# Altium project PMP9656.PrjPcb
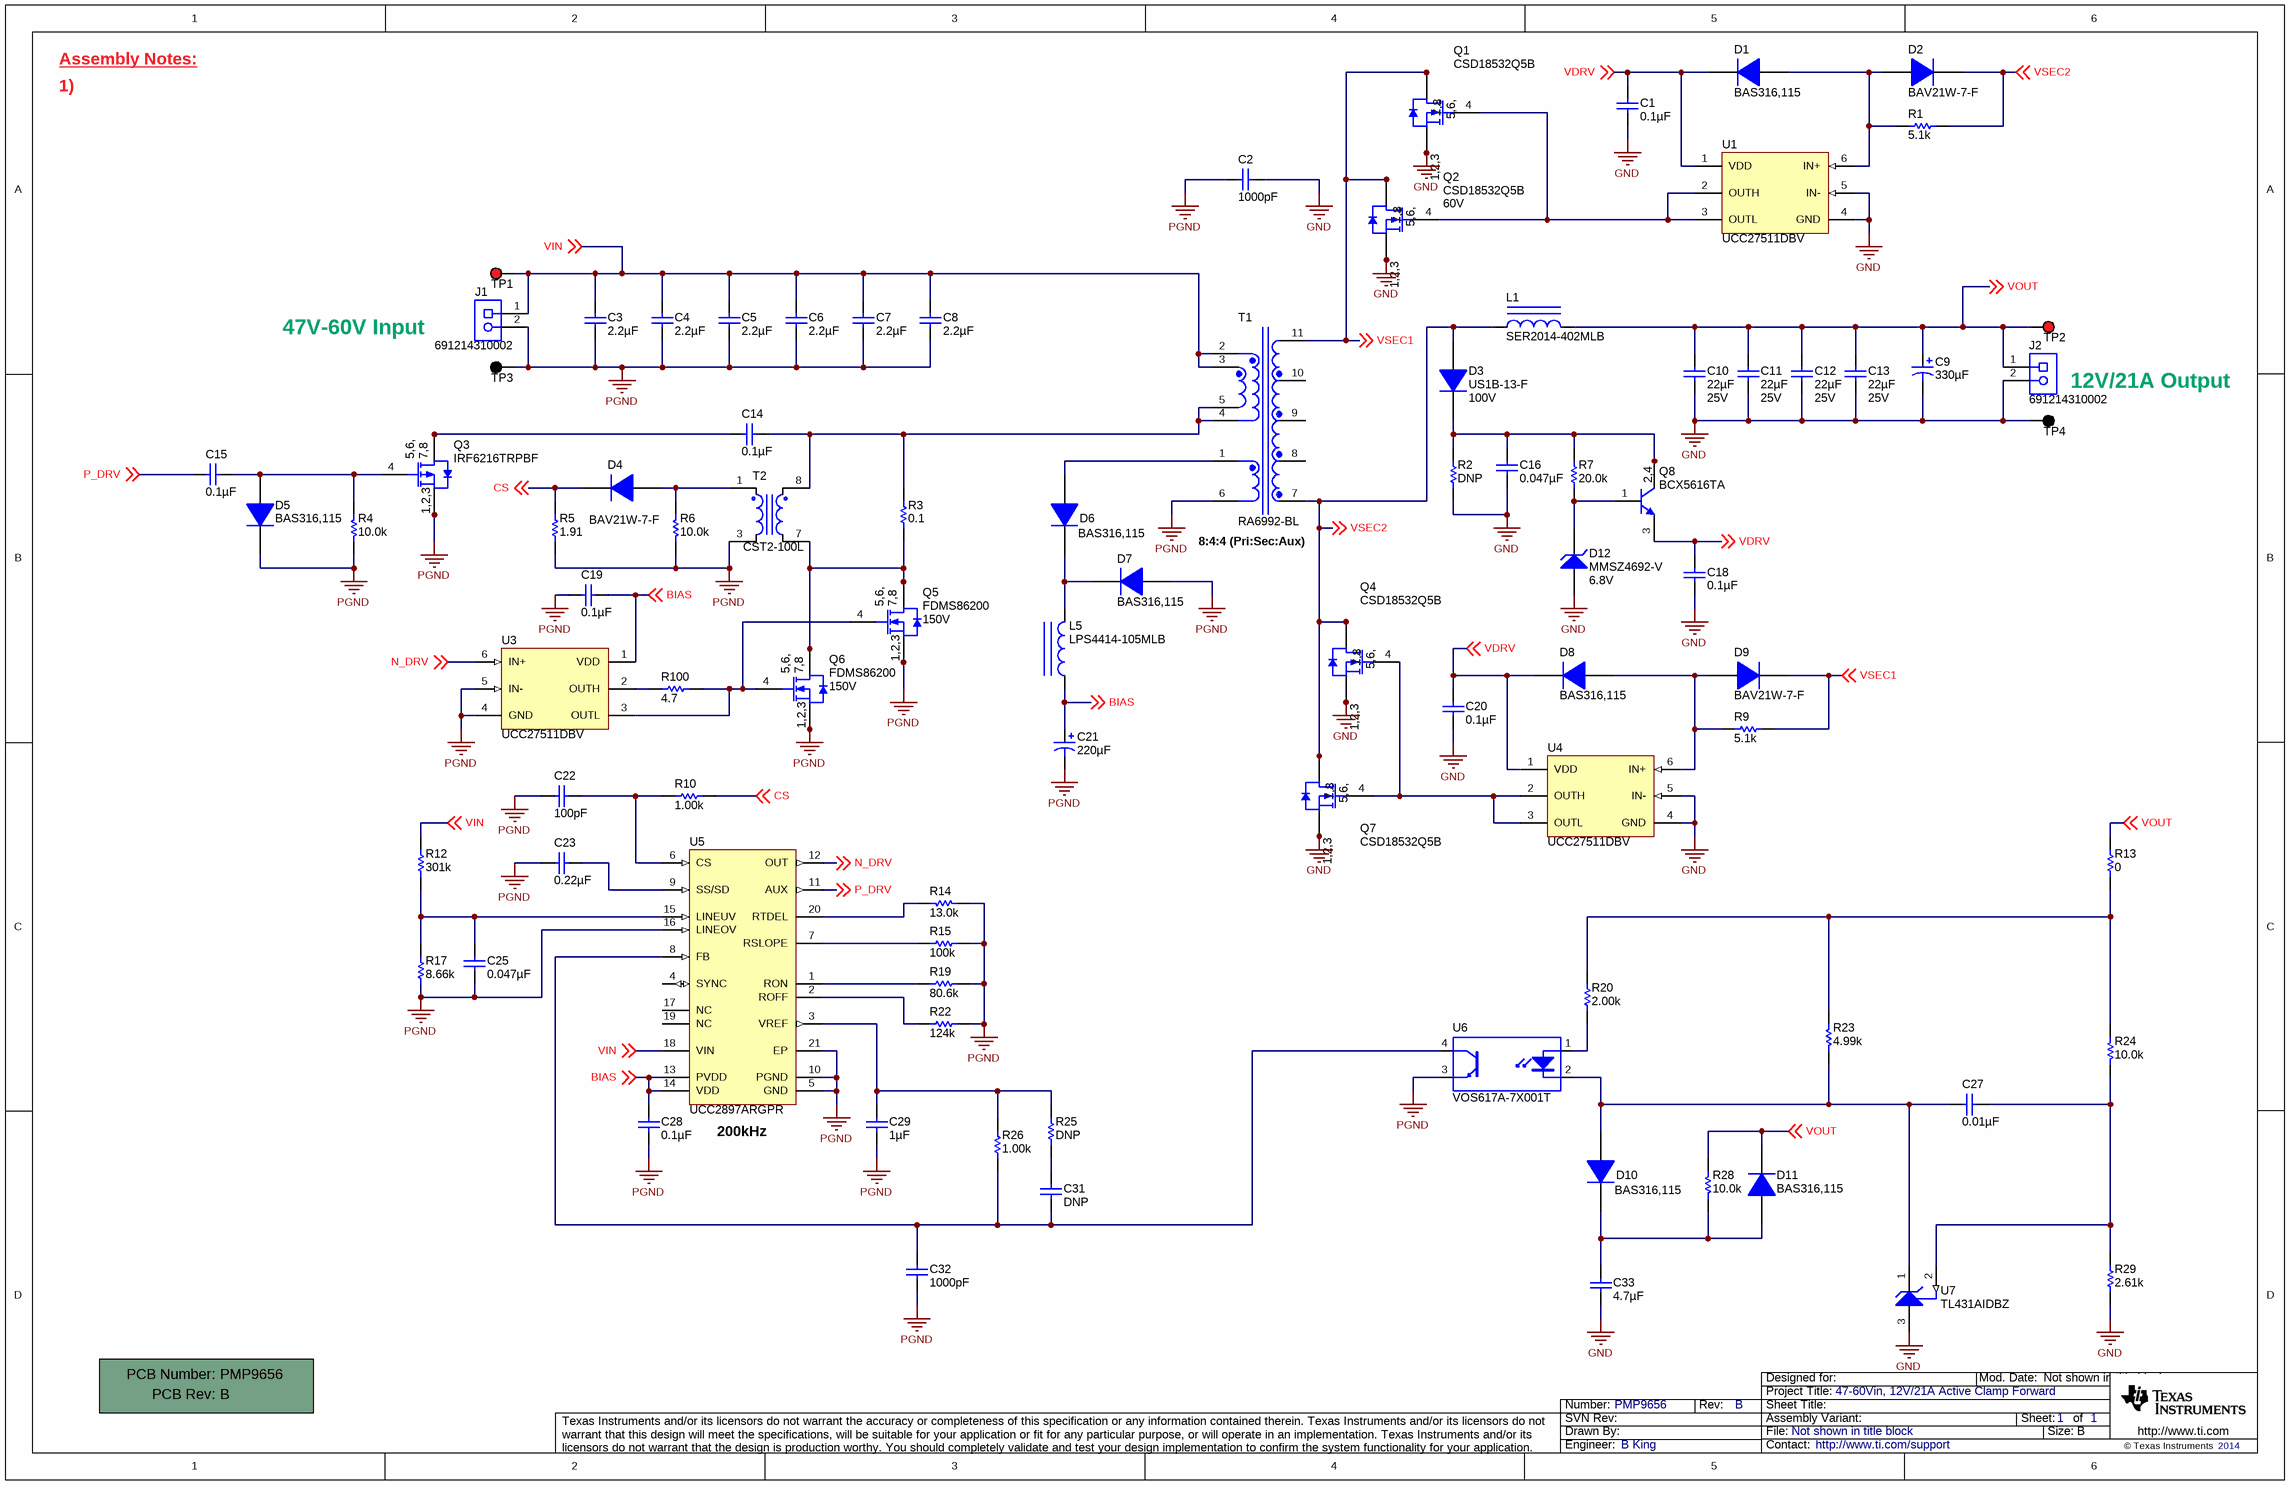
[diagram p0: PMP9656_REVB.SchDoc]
TechSupport: http://www.ti.com/support; SCH_Rev: B; PRJ_Title: 47-60Vin, 12V/21A Active Clamp Forward; PRJ_Number: PMP9656; PRJ_Engineer: B King; PCB_Rev: B; PCB_Layout: B King; CopyrightYear: 2014
1 sheet, 90 parts. Net scope: global (net labels, ports and power ports of the same name join across sheets).
Board file: PMP9656_REVB.PcbDoc

## Sheet PMP9656_REVB.SchDoc
size 431 x 279 mm; Date: Not shown in title block; ApprovedBy: Not shown in title block; CheckedBy: Not shown in title block; Author: Not shown in title block; CompanyName: Not shown in title block; Engineer: Not shown in title block; Organization: Not shown in title block; Address1: Not shown in title block; Address2: Not shown in title block; Address3: Not shown in title block; Address4: Not shown in title block; DocumentNumber: 1; Revision: Use project parameter SCH_Rev; SheetNumber: 1; SheetTotal: 1; PageSetup: Record=PageOptions¦CenterHorizontal=True¦CenterVertical=True¦PrintScale=1.00¦XCorrection=1.00¦YCorrection=1.00¦PrintKind=0¦BorderSize=5000000¦LeftOffset=0¦BottomOffset=0¦Orientation=2¦PaperLength=1000¦PaperWidth=1000¦Scale=100¦PaperSource=15¦PrintQuality=600¦MediaType=1¦DitherType=10¦PaperKind=Letter¦PrintScaleMode=1

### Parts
!PCB1  Printed Circuit Board  (value not drawn)  (mechanical)
C1  ValueDisplayed: 0.1µF  [0402L]  (hidden comment: C1005X7R1H104M)
C2  ValueDisplayed: 1000pF  [1808_L]  (hidden comment: STD)
C3  ValueDisplayed: 2.2µF  [1210L]  (hidden comment: GRM32ER72A225KA35L)
C4  ValueDisplayed: 2.2µF  [1210L]  (hidden comment: GRM32ER72A225KA35L)
C5  ValueDisplayed: 2.2µF  [1210L]  (hidden comment: GRM32ER72A225KA35L)
C6  ValueDisplayed: 2.2µF  [1210L]  (hidden comment: GRM32ER72A225KA35L)
C7  ValueDisplayed: 2.2µF  [1210L]  (hidden comment: GRM32ER72A225KA35L)
C8  ValueDisplayed: 2.2µF  [1210L]  (hidden comment: GRM32ER72A225KA35L)
C9  ValueDisplayed: 330µF  [SM_RADIAL_10AMM]  (hidden comment: 16SVP330M)
C10  ValueDisplayed: 22µF  Value2: 25V  [1210L]  (hidden comment: GRM32ER61E226KE15L)
C11  ValueDisplayed: 22µF  Value2: 25V  [1210L]  (hidden comment: GRM32ER61E226KE15L)
C12  ValueDisplayed: 22µF  Value2: 25V  [1210L]  (hidden comment: GRM32ER61E226KE15L)
C13  ValueDisplayed: 22µF  Value2: 25V  [1210L]  (hidden comment: GRM32ER61E226KE15L)
C14  ValueDisplayed: 0.1µF  [1206L]  (hidden comment: C3216X7R2E104K)
C15  ValueDisplayed: 0.1µF  [0402L]  (hidden comment: C1005X7R1H104M)
C16  ValueDisplayed: 0.047µF  [0805L]  (hidden comment: C2012X7R2A473K)
C18  ValueDisplayed: 0.1µF  [0402L]  (hidden comment: GRM155R61H104ME14D)
C19  ValueDisplayed: 0.1µF  [0402L]  (hidden comment: C1005X7R1H104M)
C20  ValueDisplayed: 0.1µF  [0402L]  (hidden comment: C1005X7R1H104M)
C21  ValueDisplayed: 220µF  [SM_RADIAL_D8]  (hidden comment: EEE-FK1C221XP)
C22  ValueDisplayed: 100pF  [0402L]  (hidden comment: CC0402KRX7R9BB101)
C23  ValueDisplayed: 0.22µF  [0402L]  (hidden comment: GRM155R61A224KE19D)
C25  ValueDisplayed: 0.047µF  [0402L]  (hidden comment: GRM155R71E473KA88D)
C27  ValueDisplayed: 0.01µF  [0402L]  (hidden comment: C1005X7R1E103K)
C28  ValueDisplayed: 0.1µF  [0402L]  (hidden comment: C1005X7R1H104M)
C29  ValueDisplayed: 1µF  [0402L]  (hidden comment: GRM155R61A105KE15D)
C31  value DNP  [0402L]  (hidden comment: N/A)
C32  ValueDisplayed: 1000pF  [0402L]  (hidden comment: C1005X7R1H102K)
C33  ValueDisplayed: 4.7µF  [1206L]  (hidden comment: C3216X7R1E475K)
D1  BAS316,115  [sod-323]
D2  BAV21W-7-F  [SOD-123]
D3  US1B-13-F  value 100V  [SMA]
D4  BAV21W-7-F  [SOD-123]
D5  BAS316,115  [sod-323]
D6  BAS316,115  [sod-323]
D7  BAS316,115  [sod-323]
D8  BAS316,115  [sod-323]
D9  BAV21W-7-F  [SOD-123]
D10  BAS316,115  [sod-323]
D11  BAS316,115  [sod-323]
D12  MMSZ4692-V  value 6.8V  [SOD-123]
J1  691214310002  [Wurth_691214310002]
J2  691214310002  [Wurth_691214310002]
L1  SER2014-402MLB  [SER2014]
L5  LPS4414-105MLB  [LPS4414]
Q1  CSD18532Q5B  [TRANS_NexFET_Q5B]
Q2  CSD18532Q5B  value 60V  [TRANS_NexFET_Q5B]
Q3  IRF6216TRPBF  [SO-8L]
Q4  CSD18532Q5B  [TRANS_NexFET_Q5B]
Q5  FDMS86200  value 150V  [TRANS_Fairchild_PQFN08A]
Q6  FDMS86200  value 150V  [TRANS_Fairchild_PQFN08A]
Q7  CSD18532Q5B  [TRANS_NexFET_Q5B]
Q8  BCX5616TA  [SOT-89-3]
R1  value 5.1k  [0805L]  (hidden comment: CRCW08055K10JNEA)
R2  value DNP  [1210L]  (hidden comment: N/A)
R3  value 0.1  [0805L]  (hidden comment: ERJ-6RSJR10V)
R4  value 10.0k  [0402L]  (hidden comment: CRCW040210K0FKED)
R5  value 1.91  [0805L]  (hidden comment: RC0805FR-071R91L)
R6  value 10.0k  [0402L]  (hidden comment: CRCW040210K0FKED)
R7  value 20.0k  [0805L]  (hidden comment: CRCW080520K0FKEA)
R9  value 5.1k  [0805L]  (hidden comment: CRCW08055K10JNEA)
R10  value 1.00k  [0402L]  (hidden comment: CRCW04021K00FKED)
R12  value 301k  [0402L]  (hidden comment: CRCW0402301KFKED)
R13  value 0  [0402L]  (hidden comment: CRCW04020000Z0ED)
R14  value 13.0k  [0402L]  (hidden comment: CRCW040213K0FKED)
R15  value 100k  [0402L]  (hidden comment: CRCW0402100KFKED)
R17  value 8.66k  [0402L]  (hidden comment: CRCW04028K66FKED)
R19  value 80.6k  [0402L]  (hidden comment: CRCW040280K6FKED)
R20  value 2.00k  [0402L]  (hidden comment: CRCW04022K00FKED)
R22  value 124k  [0402L]  (hidden comment: CRCW0402124KFKED)
R23  value 4.99k  [0402L]  (hidden comment: CRCW04024K99FKED)
R24  value 10.0k  [0402L]  (hidden comment: CRCW040210K0FKED)
R25  value DNP  [0402L]  (hidden comment: N/A)
R26  value 1.00k  [0402L]  (hidden comment: CRCW04021K00FKED)
R28  value 10.0k  [0402L]  (hidden comment: CRCW040210K0FKED)
R29  value 2.61k  [0402L]  (hidden comment: CRCW04022K61FKED)
R100  value 4.7  [0402L]  (hidden comment: CRCW04024R70JNED)
T1  RA6992-BL  [Coilcraft_RA6992-BL]
T2  CST2-100L  [XFMR_COILCRAFT_8X8p13MM6P]
TP1  5000  [Keystone5000]  (value not drawn)
TP2  5000  [Keystone5000]  (value not drawn)
TP3  5011  [Keystone5011]  (value not drawn)
TP4  5011  [Keystone5011]  (value not drawn)
U1  UCC27511DBV  [DBV0006A_M]
U3  UCC27511DBV  [DBV0006A_M]
U4  UCC27511DBV  [DBV0006A_M]
U5  UCC2897ARGPR  [RGP0020D]
U6  VOS617A-7X001T  [SSOP-4_VISHAY]
U7  TL431AIDBZ  [DBZ0003A_N]

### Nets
GND: C1.2 C2.1 C9.2(-) C10.2 C11.2 C12.2 C13.2 C16.2 C18.2 C20.2 C33.2 D12.2(A) J2.2 Q1.1(S) Q1.2(S) Q1.3(S) Q2.1(S) Q2.2(S) Q2.3(S) Q4.1(S) Q4.2(S) Q4.3(S) Q7.1(S) Q7.2(S) Q7.3(S) R2.1 R29.1 TP4.1 U1.4(GND) U1.5(IN-) U4.4(GND) U4.5(IN-) U7.3(ANODE)
PGND: C2.2 C3.2 C4.2 C5.2 C6.2 C7.2 C8.2 C19.1 C21.2(-) C22.1 C23.1 C25.1 C28.2 C29.2 C32.2 D5.1(K) D7.2(A) J1.2 Q3.1(S) Q3.2(S) Q3.3(S) Q5.1(S) Q5.2(S) Q5.3(S) Q6.1(S) Q6.2(S) Q6.3(S) R4.1 R5.1 R6.1 R14.1 R15.1 R17.1 R19.1 R22.1 T1.6 T2.3 TP3.1 U3.4(GND) U3.5(IN-) U5.5(GND) U5.10(PGND) U5.16(LINEOV) U5.21(EP) U6.3(E)
BIAS: C19.2 C21.1(+) C28.1 L5.1 U3.1(VDD) U5.13(PVDD) U5.14(VDD) ; off-sheet BIAS
CS: D4.1(K) R5.2 R10.1 ; off-sheet CS
N_DRV: U3.6(IN+) U5.12(OUT) ; off-sheet N_DRV
P_DRV: C15.1 U5.11(AUX) ; off-sheet P_DRV
VDRV: C1.1 C18.1 C20.1 D1.1(K) D8.1(K) Q8.3(E) U1.1(VDD) U4.1(VDD) ; off-sheet VDRV
VIN: C3.1 C4.1 C5.1 C6.1 C7.1 C8.1 J1.1 R12.2 T1.2 T1.3 TP1.1 U5.18(VIN) ; off-sheet VIN
VOUT: C9.1(+) C10.1 C11.1 C12.1 C13.1 D11.1(K) J2.1 L1.2 R13.1 R28.2 TP2.1 ; off-sheet VOUT
VSEC1: D9.1(K) Q1.5(D) Q1.6(D) Q1.7(D) Q1.8(D) Q2.5(D) Q2.6(D) Q2.7(D) Q2.8(D) R9.1 T1.11 ; off-sheet VSEC1
VSEC2: D2.1(K) D3.2(A) L1.1 Q4.5(D) Q4.6(D) Q4.7(D) Q4.8(D) Q7.5(D) Q7.6(D) Q7.7(D) Q7.8(D) R1.1 T1.7 ; off-sheet VSEC2
NetC14_1: C14.1 Q3.5(D) Q3.6(D) Q3.7(D) Q3.8(D)
NetC14_2: C14.2 R3.2 T1.4 T1.5 T2.8
NetC15_2: C15.2 D5.2(A) Q3.4(G) R4.2
NetC16_1: C16.1 D3.1(K) Q8.2(C) Q8.4(C) R2.2 R7.2
NetC22_2: C22.2 R10.2 U5.6(CS)
NetC23_2: C23.2 U5.9(SS/SD)
NetC25_2: C25.2 R12.1 R17.2 U5.15(LINEUV)
NetC27_1: C27.1 D10.2(A) R23.1 U6.2(K) U7.1(CATHODE)
NetC27_2: C27.2 R24.1 R29.2 U7.2(REF)
NetC29_1: C29.1 R25.1 R26.1 U5.3(VREF)
NetC31_1: C31.1 C32.1 R26.2 U5.8(FB) U6.4(C)
NetC31_2: C31.2 R25.2
NetC33_1: C33.1 D10.1(K) D11.2(A) R28.1
NetD1_2: D1.2(A) D2.2(A) R1.2 U1.6(IN+)
NetD4_2: D4.2(A) R6.2 T2.1
NetD6_1: D6.1(K) D7.1(K) L5.2
NetD6_2: D6.2(A) T1.1
NetD8_2: D8.2(A) D9.2(A) R9.2 U4.6(IN+)
NetD12_1: D12.1(K) Q8.1(B) R7.1
NetQ1_4: Q1.4(G) Q2.4(G) U1.2(OUTH) U1.3(OUTL)
NetQ4_4: Q4.4(G) Q7.4(G) U4.2(OUTH) U4.3(OUTL)
NetQ5_4: Q5.4(G) Q6.4(G) R100.2 U3.3(OUTL)
NetQ5_5: Q5.5(D) Q5.6(D) Q5.7(D) Q5.8(D) Q6.5(D) Q6.6(D) Q6.7(D) Q6.8(D) R3.1 T2.7
NetR13_2: R13.2 R20.2 R23.2 R24.2
NetR14_2: R14.2 U5.20(RTDEL)
NetR15_2: R15.2 U5.7(RSLOPE)
NetR19_2: R19.2 U5.1(RON)
NetR20_1: R20.1 U6.1(A)
NetR22_2: R22.2 U5.2(ROFF)
NetR100_1: R100.1 U3.2(OUTH)

Not connected (* = marked no-connect by the designer): T1 8 9 10; U5 4(SYNC) 17(NC) 19(NC)

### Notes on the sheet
- Assembly Notes:
- 1)
- 47V-60V Input
- 12V/21A Output
- (near T1) 8:4:4 (Pri:Sec:Aux)
- (near U5) 200kHz

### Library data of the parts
!PCB1 = PCB: Manufacturer: Any; PartNumber: PMP9656; SymbolCreator: a0412235
C1 C15 C19 C20 C28 = C1005X7R1H104M: CAP, CERM, 0.1uF, 50V, +/-20%, C0G/NP0, 0402; Manufacturer: TDK; Polarized: N; CompType: Capacitor; U/M: EA; Cap_F: 0.0000001; Tolerance_%: 20; Value1: Unknown; VDC_V: 50; TaMin_C: -55; TaMax_C: 125; Cap_Case: 0402
C2 = VJ1808Y102KXEAT5Z: CAP, CERM, 1000pF, 3kV, 1808; Polarized: N; CompType: Capacitor; U/M: EA; Cap_F: 0.000000001; Tolerance_%: 10; Value1: Unknown; TempCo: X7R; TaMin_C: -55; TaMax_C: 125; Cap_Case: 1808
C3-C8 = GRM32ER72A225KA35L: CAP, CERM, 2.2uF, 100V, +/-10%, X7R, 1210; Manufacturer: MuRata; Polarized: N; CompType: Capacitor; U/M: EA; Cap_F: 0.0000022; Tolerance_%: 10; ESR_Ohm: 0.007; Value1: 0.007 ohm; VDC_V: 100; IRMS_A: 4.4; TaMin_C: -55; TaMax_C: 125; Cap_Case: 1210
C9 = 16SVP330M: CAP, OS-CON, 330uF, 16V, +/-20%, 0.016 ohm, 10x10.3 SMD; Manufacturer: Sanyo; Polarized: Y; CompType: Capacitor; U/M: EA; Cap_F: 0.00033; Tolerance_%: 20; VDC_V: 16; ESR_Ohm: 0.016; IRMS_A: 4.72; TaMin_C: -55; TaMax_C: 105; Cap_Case: 10.3x10.3x12.6
C10-C13 = GRM32ER61E226KE15L: CAP, CERM, 22uF, 25V, +/-10%, X5R, 1210; Manufacturer: MuRata; Polarized: N; CompType: Capacitor; U/M: EA; Cap_F: 0.000022; Tolerance_%: 10; ESR_Ohm: 0.002; Value1: 0.002 ohm; VDC_V: 25; IRMS_A: 3.67; TaMin_C: -55; TaMax_C: 85; Cap_Case: 1210
C14 = C3216X7R2E104K: CAP, CERM, 0.1uF, 250V, +/-10%, X7R, 1206; Manufacturer: TDK; Polarized: N; CompType: Capacitor; U/M: EA; Cap_F: 0.0000001; Tolerance_%: 10; ESR_Ohm: 0.0217; Value1: 0.0217 ohm; VDC_V: 250; TaMin_C: -55; TaMax_C: 125; Cap_Case: 1206
C16 = C2012X7R2A473K: CAP, CERM, 0.047uF, 100V, +/-10%, X7R, 0805; Manufacturer: TDK; Polarized: N; CompType: Capacitor; U/M: EA; Cap_F: 0.000000047; Tolerance_%: 10; ESR_Ohm: 0.0211; Value1: 0.0211 ohm; VDC_V: 100; TaMin_C: -55; TaMax_C: 125; Cap_Case: 0805
C18 = GRM155R61H104ME14D: CAP, CERM, 0.1 µF, 50 V,+/- 20%, X5R, 0402; Manufacturer: MuRata; Polarized: N; CompType: Capacitor; Value: 0.1uF; U/M: EA; Cap_F: 0.0000001; Tolerance_%: 20; VDC_V: 50; Value2: 50V; TaMin_C: -55; TaMax_C: 85; Cap_Case: 0402; SizeArea_mm2: 0.5; SizeAreaWB_mm2: 3; SizeX_mm: 1; SizeZ_mm: 0.6; AEC Category: Q200
C21 = EEE-FK1C221XP: CAP, AL, 220uF, 16V, +/-20%, 0.34 ohm, SMD; Manufacturer: Panasonic; Polarized: Y; CompType: Capacitor; U/M: EA; Cap_F: 0.00022; Tolerance_%: 20; VDC_V: 16; ESR_Ohm: 0.34; IRMS_A: 0.28; TaMin_C: -55; TaMax_C: 105; Cap_Case: D8
C22 = CC0402KRX7R9BB101: CAP, CERM, 100pF, 50V, +/-10%, X7R, 0402; Manufacturer: Yageo America; Polarized: N; CompType: Capacitor; U/M: EA; Cap_F: 0.0000000001; Tolerance_%: 10; Value1: Unknown; VDC_V: 50; TaMin_C: -55; TaMax_C: 125; Cap_Case: 0402
C23 = GRM155R61A224KE19D: CAP, CERM, 0.22uF, 10V, +/-10%, X5R, 0402; Manufacturer: MuRata; Polarized: N; CompType: Capacitor; U/M: EA; Cap_F: 0.00000022; Tolerance_%: 10; Value1: Unknown; TaMin_C: -55; TaMax_C: 85; Cap_Case: 0402
C25 = GRM155R71E473KA88D: CAP, CERM, 0.047uF, 25V, +/-10%, X7R, 0402; Manufacturer: MuRata; Polarized: N; CompType: Capacitor; U/M: EA; Cap_F: 0.000000047; Tolerance_%: 10; Value1: Unknown; VDC_V: 25; TaMin_C: -55; TaMax_C: 125; Cap_Case: 0402
C27 = C1005X7R1E103K: CAP, CERM, 0.01uF, 25V, +/-10%, X7R, 0402; Manufacturer: TDK; Polarized: N; CompType: Capacitor; U/M: EA; Cap_F: 0.00000001; Tolerance_%: 10; ESR_Ohm: 0.0623; Value1: 0.0623 ohm; VDC_V: 25; TaMin_C: -55; TaMax_C: 125; Cap_Case: 0402
C29 = GRM155R61A105KE15D: CAP, CERM, 1uF, 10V, +/-10%, X5R, 0402; Manufacturer: MuRata; Polarized: N; CompType: Capacitor; U/M: EA; Cap_F: 0.000001; Tolerance_%: 10; Value1: Unknown; TaMin_C: -55; TaMax_C: 85; Cap_Case: 0402
C31 = 04025C132KAT2A: Do Not Populate; Polarized: N; CompType: Capacitor; ValueDisplayed: 1300pF; U/M: EA; Cap_F: 0.0000000013; Tolerance_%: 10; Value1: Unknown; VDC_V: 50; Value2: 50V; TempCo: X7R; TaMin_C: -55; TaMax_C: 125; Cap_Case: 0402
C32 = C1005X7R1H102K: CAP, CERM, 1000pF, 50V, +/-10%, X7R, 0402; Manufacturer: TDK; Polarized: N; CompType: Capacitor; U/M: EA; Cap_F: 0.000000001; Tolerance_%: 10; ESR_Ohm: 0.2381; Value1: 0.2381 ohm; VDC_V: 50; TaMin_C: -55; TaMax_C: 125; Cap_Case: 0402
C33 = C3216X7R1E475K: CAP, CERM, 4.7uF, 25V, +/-10%, X7R, 1206; Manufacturer: TDK; Polarized: N; CompType: Capacitor; U/M: EA; Cap_F: 0.0000047; Tolerance_%: 10; ESR_Ohm: 0.0063; Value1: 0.0063 ohm; VDC_V: 25; TaMin_C: -55; TaMax_C: 125; Cap_Case: 1206
D1 D8 = BAS316,115: Diode, Ultrafast, 100V, 0.25A, SOD-323; Manufacturer: NXP Semiconductor; U/M: EA; Vf_V: 1.4; Io_A: 0.25; Vr_V: 100; Value2: 1.4V; TJmax_C: 150
D2 D4 D9 = BAV21W-7-F: Diode, Switching, 200V, 0.2A, SOD-123; Manufacturer: Diodes Inc.; Value: 1.25V; U/M: EA; Vf_V: 1.25; Io_A: 0.2; Vr_V: 200; TJmax_C: 150
D3 = US1B-13-F: Diode, Ultrafast, 100V, 1A, SMA; Manufacturer: Diodes Inc.; U/M: EA; Vf_V: 1; Vr_V: 100; Value2: 1V; TJmax_C: 150; RJC_CperW: 30
D5-D7 D10 D11 = BAS316,115: Diode, Ultrafast, 100V, 0.25A, SOD-323; Manufacturer: NXP Semiconductor; Value: 1.4V; U/M: EA; Vf_V: 1.4; Io_A: 0.25; Vr_V: 100; TJmax_C: 150
D12 = MMSZ4692-V: Diode, Zener, 6.8V, 500mW, SOD-123; Manufacturer: Vishay-Semiconductor; SymbolCreator: a0412235; U/M: EA; Power_W: 0.5; Vz_V: 6.8; Value1: 0.5W; RJA_CperW: 67
J1 J2 = 691214310002: Terminal Block, 2x1, 3.81mm, 24-16 AWG, 10A, 300VAC, TH; Manufacturer: Wurth Elektronik eiSos; SymbolCreator: a0412235; U/M: EA
L1 = SER2014-402MLB: Inductor, Shielded E Core, Ferrite, 4uH, 25A, 0.00194 ohm, SMD; Manufacturer: Coilcraft; Ind_H: 4.0E-6; ValueDisplayed: 4µH; Imax_A: 25; Irms: 27A @ 40C rise; Isat: 25A @ 10% inductance drop; U/M: EA
L5 = LPS4414-105MLB: Inductor, Shielded Drum Core, Ferrite, 1mH, 0.11A, 16.3 ohm, SMD; Manufacturer: Coilcraft; Ind_H: 1.0E-3; Imax_A: 0.11; Irms: 0.13A @ 40C rise; Isat: 0.106A @ 30% inductance drop; DCR_ohm: 16.3; U/M: EA
Q1 Q2 Q4 Q7 = CSD18532Q5B: MOSFET, N-CH, 60V, 172A, SON 5x6mm; Manufacturer: Texas Instruments; Alternate Manufacturer: None; U/M: EA; ChType: N; VdsMax_V: 60; Value1: 3.3 ohm; Rdson45_Ohm: 3.3; Value2: 27 nC; QgTyp_nC: 27; Vgs_V: 1.6; IdsMax_A: 172
Q3 = IRF6216TRPBF: MOSFET, P-CH, -150V, -2.2A, SO-8; Manufacturer: International Rectifier; Alternate Manufacturer: None; U/M: EA; ChType: P; VdsMax_V: -150; Value1: ? ohm; Value2: 15 nC; QgTyp_nC: 15; Vgs_V: 20; IdsMax_A: -2.2
Q5 Q6 = FDMS86200: MOSFET, N-CH, 150V, 35A, PQFN08A; Manufacturer: Fairchild Semiconductor; Alternate Manufacturer: None; U/M: EA; ChType: N; VdsMax_V: 150; Value1: 101 ohm; Rdson45_Ohm: 101; Value2: 33 nC; QgTyp_nC: 33; Vgs_V: 20; IdsMax_A: 35
Q8 = BCX5616TA, Diodes Inc.: Transistor, NPN, 80V, 1A, SOT-89; CompType: BJT; PNP: 0; NPN: 1; Vceo_V: 80; Vcesat1_V: 0.5; Value: 0.5V; HfeMax: 250; TaMin_C: -65; TaMax_C: 150; U/M: EA
R1 R9 = CRCW08055K10JNEA: RES, 5.1k ohm, 5%, 0.125W, 0805; Manufacturer: Vishay-Dale; CompType: Resistor; Res_ohm: 5100; Value_Code: 5k10; Tolerance_%: 5; Power_W: 0.125; VDC_V: 150; TempCo: 200 ppm/C; EIA_Code: E24; U/M: EA
R2 = ERJ-L14KF10CU: Do Not Populate; CompType: Resistor; Res_ohm: 0.1; Value_Code: R100; Tolerance_%: 1; Value1: 1%; Power_W: 0.33; Value2: 0.33W; TempCo: 100 ppm/C; EIA_Code: E96; U/M: EA
R3 = ERJ-6RSJR10V: RES, 0.1 ohm, 5%, 0.125W, 0805; Manufacturer: Panasonic; CompType: Resistor; Value_Code: R100; Tolerance_%: 5; Power_W: 0.125; TempCo: 250 ppm/C; EIA_Code: E24; U/M: EA
R4 R6 R24 R28 = CRCW040210K0FKED: RES, 10.0k ohm, 1%, 0.063W, 0402; Manufacturer: Vishay-Dale; CompType: Resistor; Res_ohm: 10000; Value_Code: 10k0; Tolerance_%: 1; Power_W: 0.063; VDC_V: 50; TempCo: 100 ppm/C; EIA_Code: E96; U/M: EA
R5 = RC0805FR-071R91L: RES, 1.91 ohm, 1%, 0.125W, 0805; Manufacturer: Yageo America; CompType: Resistor; Value_Code: 1R91; Tolerance_%: 1; Power_W: 0.125; VDC_V: 150; TempCo: 200 ppm/C; EIA_Code: E96; U/M: EA
R7 = CRCW080520K0FKEA: RES, 20.0k ohm, 1%, 0.125W, 0805; Manufacturer: Vishay-Dale; CompType: Resistor; Res_ohm: 20000; Value_Code: 20k0; Tolerance_%: 1; Power_W: 0.125; VDC_V: 150; TempCo: 100 ppm/C; EIA_Code: E96; U/M: EA
R10 R26 = CRCW04021K00FKED: RES, 1.00k ohm, 1%, 0.063W, 0402; Manufacturer: Vishay-Dale; CompType: Resistor; Res_ohm: 1000; Value_Code: 1k00; Tolerance_%: 1; Power_W: 0.063; VDC_V: 50; TempCo: 100 ppm/C; EIA_Code: E96; U/M: EA
R12 = CRCW0402301KFKED: RES, 301k ohm, 1%, 0.063W, 0402; Manufacturer: Vishay-Dale; CompType: Resistor; Res_ohm: 301000; Tolerance_%: 1; Power_W: 0.063; VDC_V: 50; TempCo: 100 ppm/C; EIA_Code: E96; U/M: EA
R13 = CRCW04020000Z0ED: RES, 0 ohm, 5%, 0.063W, 0402; Manufacturer: Vishay-Dale; CompType: Resistor; Value_Code: 0000; Tolerance_%: 5; Power_W: 0.063; VDC_V: 50; TempCo: 200 ppm/C; EIA_Code: E24; U/M: EA
R14 = CRCW040213K0FKED: RES, 13.0k ohm, 1%, 0.063W, 0402; Manufacturer: Vishay-Dale; CompType: Resistor; Res_ohm: 13000; Value_Code: 13k0; Tolerance_%: 1; Power_W: 0.063; VDC_V: 50; TempCo: 100 ppm/C; EIA_Code: E96; U/M: EA
R15 = CRCW0402100KFKED: RES, 100k ohm, 1%, 0.063W, 0402; Manufacturer: Vishay-Dale; CompType: Resistor; Res_ohm: 100000; Tolerance_%: 1; Power_W: 0.063; VDC_V: 50; TempCo: 100 ppm/C; EIA_Code: E96; U/M: EA
R17 = CRCW04028K66FKED: RES, 8.66k ohm, 1%, 0.063W, 0402; Manufacturer: Vishay-Dale; CompType: Resistor; Res_ohm: 8660; Value_Code: 8k66; Tolerance_%: 1; Power_W: 0.063; VDC_V: 50; TempCo: 100 ppm/C; EIA_Code: E96; U/M: EA
R19 = CRCW040280K6FKED: RES, 80.6k ohm, 1%, 0.063W, 0402; Manufacturer: Vishay-Dale; CompType: Resistor; Res_ohm: 80600; Value_Code: 80k6; Tolerance_%: 1; Power_W: 0.063; VDC_V: 50; TempCo: 100 ppm/C; EIA_Code: E96; U/M: EA
R20 = CRCW04022K00FKED: RES, 2.00k ohm, 1%, 0.063W, 0402; Manufacturer: Vishay-Dale; CompType: Resistor; Res_ohm: 2000; Value_Code: 2k00; Tolerance_%: 1; Power_W: 0.063; VDC_V: 50; TempCo: 100 ppm/C; EIA_Code: E96; U/M: EA
R22 = CRCW0402124KFKED: RES, 124k ohm, 1%, 0.063W, 0402; Manufacturer: Vishay-Dale; CompType: Resistor; Res_ohm: 124000; Tolerance_%: 1; Power_W: 0.063; VDC_V: 50; TempCo: 100 ppm/C; EIA_Code: E96; U/M: EA
R23 = CRCW04024K99FKED: RES, 4.99k ohm, 1%, 0.063W, 0402; Manufacturer: Vishay-Dale; CompType: Resistor; Res_ohm: 4990; Value_Code: 4k99; Tolerance_%: 1; Power_W: 0.063; VDC_V: 50; TempCo: 100 ppm/C; EIA_Code: E96; U/M: EA
R25 = CRCW0402133RFKED: Do Not Populate; CompType: Resistor; Res_ohm: 133; Value_Code: 133R; Tolerance_%: 1; Value1: 1%; Power_W: 0.063; Value2: 0.063W; VDC_V: 50; TempCo: 100 ppm/C; EIA_Code: E96; U/M: EA
R29 = CRCW04022K61FKED: RES, 2.61k ohm, 1%, 0.063W, 0402; Manufacturer: Vishay-Dale; CompType: Resistor; Res_ohm: 2610; Value_Code: 2k61; Tolerance_%: 1; Power_W: 0.063; VDC_V: 50; TempCo: 100 ppm/C; EIA_Code: E96; U/M: EA
R100 = CRCW04024R70JNED: RES, 4.7 ohm, 5%, 0.063W, 0402; Manufacturer: Vishay-Dale; CompType: Resistor; Value_Code: 4R70; Tolerance_%: 5; Power_W: 0.063; VDC_V: 50; TempCo: 200 ppm/C; EIA_Code: E24; U/M: EA
T1 = RA6992-BL: Transformer, 50uH, SMT; Manufacturer: Coilcraft; SymbolCreator: a0411947; DCR_Ohm: 0.0138; LeakageL: 0.25uH; U/M: EA
T2 = CST2-100L: Transformer, 2000uH, SMT; Manufacturer: Coilcraft; SymbolCreator: a0799628; U/M: EA
TP1 TP2 = 5000: Test Point, Miniature, Red, TH; Manufacturer: Keystone; CompType: Test Point Loop; U/M: EA
TP3 TP4 = 5011: Test Point, Multipurpose, Black, TH; Manufacturer: Keystone; CompType: Test Point Loop; U/M: EA
U1 U3 U4 = UCC27511DBV: Single-Channel High-Speed Low-Side Gate Driver (with 4-A Peak Source and 8-A Peak Sink), DBV0006A; Alternate Manufacturer: None; Manufacturer: Texas Instruments; SymbolCreator: a0411947; CompType: IC; U/M: EA
U5 = UCC2897ARGPR: Advanced Active Clamp PWM Controller with Current Control, -40 to +125 degC, 20-pin QFN (RGP), Green (RoHS & no Sb/Br); Manufacturer: Texas Instruments; Alternate Manufacturer: None; Alternate PartNumber: Equivalent; Frequency(Max)(kHz): 1000; Rating: Catalog; Regulated Outputs(#): 1
U6 = VOS617A-7X001T: OptoCoupler, Phototransitor, 80-160%, SSOP-4; Manufacturer: Vishay-Semiconductor; U/M: EA
U7 = TL431AIDBZ: PRECISION PROGRAMMABLE REFERENCE, DBZ0003A; Alternate Manufacturer: None; Manufacturer: Texas Instruments; SymbolCreator: a0412235; CompType: IC; U/M: EA

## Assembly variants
001: not fitted FID1 FID2 FID3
